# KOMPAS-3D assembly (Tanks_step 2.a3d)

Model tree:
1. Plane XY
2. Plane ZX
3. Plane ZY
4. X Axis
5. Y Axis
6. Z Axis
7. Origin
8. Polyline:418
9. Polyline:448
10. Polyline:538
11. Polyline:568
12. Polyline:569
13. Polyline:570
14. Point:1
     X = -6791.83; Y = -1500; Z = 1.7112e-08; Coordinate.X = -6791.83; Coordinate.Y = -1500; Coordinate.Z = 1.7112e-08
15. Point:2
     X = -1606; Y = -500; Move.X = -500; Distance = 500
16. Point:3
     X = -1606; Y = -2500; Z = 700; Move.X = -500; Move.Z = 4.09273e-09; Distance = 500
17. Point:9  (labels: C:\Program Files\ASCON\KOMPAS-3D V10\Sys\graphic.lyt; Pipe Dn 50; Pipe_Tanks_step 2_70.m3d; Pipe_Tanks_step 2_72.m3d)
     X = -3769.83; Y = 762.724; Z = 3112; Move.Z = 500; Distance = 500; Orientation = 2

Referenced files in C:\Documents and Settings\kashirsky\Мои документы\Camtasia Studio\Pipelines3D\Tanks\: Tank 2.a3d, Tank 1.a3d, Piping_Joint_150_1000.m3d, Piping_Flange_150_1000.m3d, Piping_Joint_50_1000.m3d, Piping_Flange_50_1000.m3d
Referenced files in C:\Documents and Settings\kashirsky\Мои документы\Camtasia Studio\Pipelines3D\Tanks\Tanks_step 2_Pipes\: Pipe_Tanks_step 2_70.m3d, Pipe_Tanks_step 2_72.m3d, Pipe_Tanks_step 2_73.m3d, Pipe_Tanks_step 2_75.m3d, Pipe_Tanks_step 2_80.m3d, Pipe_Tanks_step 2_81.m3d, Pipe_Tanks_step 2_82.m3d, Pipe_Tanks_step 2_84.m3d, Pipe_Tanks_step 2_85.m3d, Pipe_Tanks_step 2_86.m3d, Pipe_Tanks_step 2_87.m3d, Pipe_Tanks_step 2_88.m3d, Pipe_Tanks_step 2_89.m3d
Referenced files in C:\Program Files\ASCON\KOMPAS-3D V10\Libs\Piping\LOAD\: Piping_C_Bend_90_50_1000.m3d, Piping_C_TBend_50_1000.m3d
Referenced files in C:\Program Files\ASCON\KOMPAS-3D V10\Libs\Piping\Equipment\Valve\: Piping_Valve_50_1000.m3d
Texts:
  Three Point Plane
  Plane at Angle
  Line and Point Plane
  Axis through Two Vertices
  Axis of Feature
  Axis of Conical Surface
  Axis through Edge
  Trim by Surface
  Trim by Sketch
  Intersection Axis of Two Planes
  Two Line Plane
  Line and Face Plane
  Pattern by Sample
  Point in CM
  Feature with No History
  Linear Dimension from Line to Point
  Surface Finish Symbol
  Geometric Tolerance Symbol
  Текст на чертеже
  Линия-выноска #1
  Линия-выноска #2
  Линия-выноска #3
  Отклонения формы и база
  Марка координационной оси
  Марка/позиционное обозначение с линией-выноской
  Марка/позиционное обозначение на линии
  Марка/позиционное обозначение без линии-выноски
  Tank 2
  Tank 1
  Joint Dn 150
  Steel ASTM A295
  Flange Dn 150
  Прокладка Dy 50
  Flange Dn 50
  Трубы - объекты
  Pipe Dn 50
  Трубы - описания
  Элементы - объекты
  Bend 90 Dn 50
  T-Bend Dn 50
  Элементы - описания
  Pipelines 3D
  Valve Dy 50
